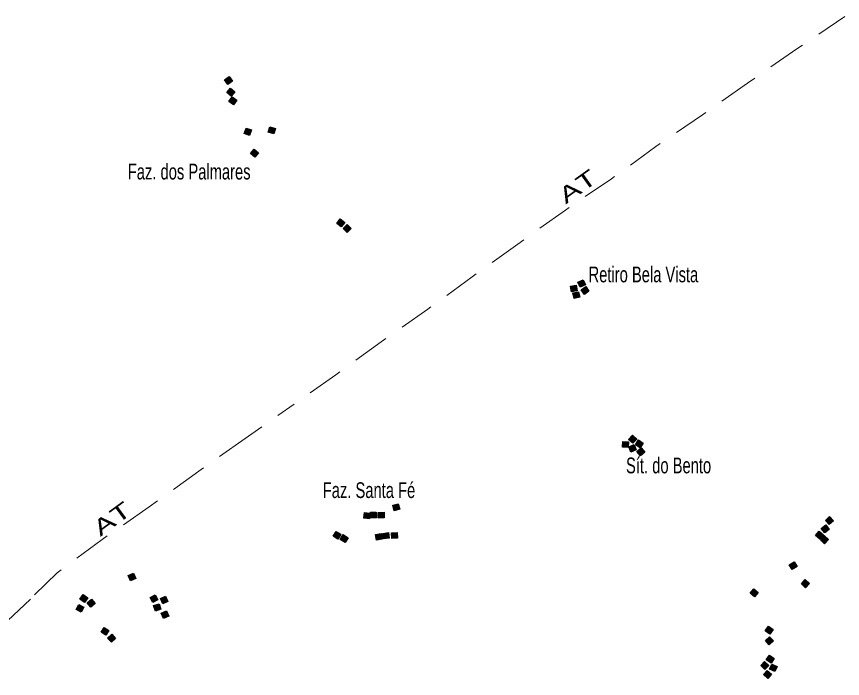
# Model space of a CAD drawing. Extents: x 679 to 705, y 7427.4 to 7455.4.
# Drawn here: x 683.784 to 687.983, y 7433.767 to 7437.132 of the extents above; entities that cross this region are included whole.
import ezdxf
from ezdxf.enums import TextEntityAlignment as Align

# ---------------------------------------------------------------- set-up
doc = ezdxf.new("R2010")
doc.units = 0
doc.header["$LTSCALE"] = 0.032
doc.linetypes.add('DOT_DASHED', pattern=[7.7, 5, -1.2, 0.3, -1.2])
doc.layers.add('2', color=7, linetype='Continuous', lineweight=25)
doc.layers.add('56', color=7, linetype='DOT_DASHED', lineweight=13)
doc.layers.add('61', color=7, linetype='Continuous')

msp = doc.modelspace()

# ---------------------------------------------------------------- hatches: boundary and pattern name
at = {"layer": '2'}
for points in [[(684.8648, 7436.8274), (684.8813, 7436.8036), (684.8575, 7436.787), (684.8409, 7436.8109)], [(684.871, 7436.7685), (684.8931, 7436.7497), (684.8743, 7436.7276), (684.8522, 7436.7465)], [(684.8804, 7436.7233), (684.9042, 7436.7066), (684.8876, 7436.6829), (684.8638, 7436.6995)], [(684.9779, 7436.5554), (684.9682, 7436.528), (684.9409, 7436.5377), (684.9505, 7436.5651)], [(685.0997, 7436.5632), (685.0913, 7436.5354), (685.0635, 7436.5439), (685.072, 7436.5716)], [(685.0135, 7436.4391), (684.9949, 7436.4169), (684.9727, 7436.4355), (684.9913, 7436.4577)], [(685.4299, 7436.1031), (685.4528, 7436.0852), (685.4349, 7436.0624), (685.4121, 7436.0803)], [(685.4441, 7436.0544), (685.4649, 7436.0746), (685.4851, 7436.0539), (685.4644, 7436.0336)], [(686.6642, 7435.7943), (686.6763, 7435.7679), (686.6499, 7435.7559), (686.6378, 7435.7822)], [(686.6296, 7435.7665), (686.6339, 7435.7378), (686.6053, 7435.7335), (686.601, 7435.7622)], [(686.6775, 7435.76), (686.6943, 7435.7364), (686.6707, 7435.7196), (686.6539, 7435.7432)], [(686.6412, 7435.7334), (686.6474, 7435.7051), (686.6191, 7435.6989), (686.6129, 7435.7272)], [(686.9152, 7435.0038), (686.9369, 7434.9846), (686.9177, 7434.9628), (686.896, 7434.982)], [(686.896, 7434.9707), (686.894, 7434.9418), (686.865, 7434.9438), (686.867, 7434.9727)], [(686.9243, 7434.9559), (686.9347, 7434.9288), (686.9076, 7434.9184), (686.8972, 7434.9455)], [(686.9467, 7434.9796), (686.9705, 7434.963), (686.954, 7434.9392), (686.9301, 7434.9558)], [(686.9602, 7434.9405), (686.9789, 7434.9184), (686.9567, 7434.8997), (686.938, 7434.9218)], [(685.7245, 7434.6554), (685.7321, 7434.6274), (685.7041, 7434.6198), (685.6965, 7434.6478)], [(685.581, 7434.6073), (685.5781, 7434.5785), (685.5492, 7434.5814), (685.5521, 7434.6102)], [(685.613, 7434.6134), (685.6138, 7434.5844), (685.5849, 7434.5835), (685.584, 7434.6125)], [(685.6521, 7434.6122), (685.6534, 7434.5832), (685.6245, 7434.5819), (685.6231, 7434.6108)], [(687.9178, 7434.5903), (687.9371, 7434.5688), (687.9156, 7434.5494), (687.8962, 7434.5709)], [(687.8981, 7434.548), (687.9158, 7434.5251), (687.8929, 7434.5074), (687.8752, 7434.5303)], [(685.4082, 7434.5152), (685.4329, 7434.5001), (685.4178, 7434.4753), (685.3931, 7434.4905)], [(685.4449, 7434.4984), (685.4695, 7434.483), (685.4541, 7434.4584), (685.4295, 7434.4738)], [(685.6381, 7434.5036), (685.642, 7434.4749), (685.6133, 7434.471), (685.6094, 7434.4997)], [(685.6744, 7434.5094), (685.6787, 7434.4807), (685.65, 7434.4764), (685.6458, 7434.5051)], [(685.7197, 7434.5094), (685.7207, 7434.4804), (685.6917, 7434.4794), (685.6907, 7434.5084)], [(687.8646, 7434.5157), (687.8867, 7434.4969), (687.8678, 7434.4749), (687.8458, 7434.4937)], [(687.8906, 7434.4933), (687.912, 7434.4737), (687.8924, 7434.4523), (687.871, 7434.4719)], [(687.7371, 7434.3607), (687.7524, 7434.3361), (687.7277, 7434.3208), (687.7124, 7434.3454)], [(684.3777, 7434.3025), (684.39, 7434.2762), (684.3638, 7434.2639), (684.3515, 7434.2902)], [(687.7933, 7434.2697), (687.815, 7434.2505), (687.7958, 7434.2288), (687.7741, 7434.248)], [(684.1218, 7434.1935), (684.1456, 7434.177), (684.1291, 7434.1531), (684.1053, 7434.1697)], [(684.4879, 7434.1932), (684.5021, 7434.1679), (684.4768, 7434.1537), (684.4626, 7434.179)], [(684.5415, 7434.1857), (684.5535, 7434.1593), (684.5271, 7434.1473), (684.5151, 7434.1737)], [(687.5333, 7434.2233), (687.5551, 7434.2041), (687.5359, 7434.1824), (687.5141, 7434.2016)], [(684.0997, 7434.1436), (684.1254, 7434.1304), (684.1122, 7434.1046), (684.0864, 7434.1179)], [(684.1649, 7434.1699), (684.1835, 7434.1476), (684.1612, 7434.1291), (684.1426, 7434.1513)], [(684.5081, 7434.147), (684.5175, 7434.1196), (684.4901, 7434.1102), (684.4806, 7434.1376)], [(684.5462, 7434.111), (684.5575, 7434.0843), (684.5308, 7434.073), (684.5195, 7434.0997)], [(684.229, 7434.0271), (684.2536, 7434.0117), (684.2382, 7433.9871), (684.2136, 7434.0025)], [(687.6075, 7434.0331), (687.6307, 7434.0156), (687.6133, 7433.9924), (687.5901, 7434.0099)], [(684.268, 7433.9925), (684.2875, 7433.9711), (684.2661, 7433.9515), (684.2465, 7433.973)], [(687.6129, 7433.9798), (687.6321, 7433.9581), (687.6103, 7433.9389), (687.5911, 7433.9607)], [(687.5875, 7433.8533), (687.6083, 7433.8331), (687.5881, 7433.8123), (687.5673, 7433.8326)], [(687.6123, 7433.8853), (687.6362, 7433.8689), (687.6199, 7433.845), (687.5959, 7433.8613)], [(687.6009, 7433.8083), (687.6224, 7433.7888), (687.6029, 7433.7673), (687.5814, 7433.7868)], [(687.6245, 7433.8407), (687.6509, 7433.8288), (687.639, 7433.8024), (687.6126, 7433.8143)]]:
    msp.add_hatch(color=256, dxfattribs=at).paths.add_polyline_path(points)

# ---------------------------------------------------------------- linework, layer by layer
for points in [[(684.8648, 7436.8274), (684.8813, 7436.8036), (684.8575, 7436.787), (684.8409, 7436.8109)], [(684.871, 7436.7685), (684.8931, 7436.7497), (684.8743, 7436.7276), (684.8522, 7436.7465)], [(684.8804, 7436.7233), (684.9042, 7436.7066), (684.8876, 7436.6829), (684.8638, 7436.6995)], [(684.9779, 7436.5554), (684.9682, 7436.528), (684.9409, 7436.5377), (684.9505, 7436.5651)], [(685.0997, 7436.5632), (685.0913, 7436.5354), (685.0635, 7436.5439), (685.072, 7436.5716)], [(685.0135, 7436.4391), (684.9949, 7436.4169), (684.9727, 7436.4355), (684.9913, 7436.4577)], [(685.4299, 7436.1031), (685.4528, 7436.0852), (685.4349, 7436.0624), (685.4121, 7436.0803)], [(685.4441, 7436.0544), (685.4649, 7436.0746), (685.4851, 7436.0539), (685.4644, 7436.0336)], [(686.6642, 7435.7943), (686.6763, 7435.7679), (686.6499, 7435.7559), (686.6378, 7435.7822)], [(686.6296, 7435.7665), (686.6339, 7435.7378), (686.6053, 7435.7335), (686.601, 7435.7622)], [(686.6775, 7435.76), (686.6943, 7435.7364), (686.6707, 7435.7196), (686.6539, 7435.7432)], [(686.6412, 7435.7334), (686.6474, 7435.7051), (686.6191, 7435.6989), (686.6129, 7435.7272)], [(686.9152, 7435.0038), (686.9369, 7434.9846), (686.9177, 7434.9628), (686.896, 7434.982)], [(686.896, 7434.9707), (686.894, 7434.9418), (686.865, 7434.9438), (686.867, 7434.9727)], [(686.9243, 7434.9559), (686.9347, 7434.9288), (686.9076, 7434.9184), (686.8972, 7434.9455)], [(686.9467, 7434.9796), (686.9705, 7434.963), (686.954, 7434.9392), (686.9301, 7434.9558)], [(686.9602, 7434.9405), (686.9789, 7434.9184), (686.9567, 7434.8997), (686.938, 7434.9218)], [(685.7245, 7434.6554), (685.7321, 7434.6274), (685.7041, 7434.6198), (685.6965, 7434.6478)], [(685.581, 7434.6073), (685.5781, 7434.5785), (685.5492, 7434.5814), (685.5521, 7434.6102)], [(685.613, 7434.6134), (685.6138, 7434.5844), (685.5849, 7434.5835), (685.584, 7434.6125)], [(685.6521, 7434.6122), (685.6534, 7434.5832), (685.6245, 7434.5819), (685.6231, 7434.6108)], [(687.9178, 7434.5903), (687.9371, 7434.5688), (687.9156, 7434.5494), (687.8962, 7434.5709)], [(687.8981, 7434.548), (687.9158, 7434.5251), (687.8929, 7434.5074), (687.8752, 7434.5303)], [(685.4082, 7434.5152), (685.4329, 7434.5001), (685.4178, 7434.4753), (685.3931, 7434.4905)], [(685.4449, 7434.4984), (685.4695, 7434.483), (685.4541, 7434.4584), (685.4295, 7434.4738)], [(685.6381, 7434.5036), (685.642, 7434.4749), (685.6133, 7434.471), (685.6094, 7434.4997)], [(685.6744, 7434.5094), (685.6787, 7434.4807), (685.65, 7434.4764), (685.6458, 7434.5051)], [(685.7197, 7434.5094), (685.7207, 7434.4804), (685.6917, 7434.4794), (685.6907, 7434.5084)], [(687.8646, 7434.5157), (687.8867, 7434.4969), (687.8678, 7434.4749), (687.8458, 7434.4937)], [(687.8906, 7434.4933), (687.912, 7434.4737), (687.8924, 7434.4523), (687.871, 7434.4719)], [(687.7371, 7434.3607), (687.7524, 7434.3361), (687.7277, 7434.3208), (687.7124, 7434.3454)], [(684.3777, 7434.3025), (684.39, 7434.2762), (684.3638, 7434.2639), (684.3515, 7434.2902)], [(687.7933, 7434.2697), (687.815, 7434.2505), (687.7958, 7434.2288), (687.7741, 7434.248)], [(684.1218, 7434.1935), (684.1456, 7434.177), (684.1291, 7434.1531), (684.1053, 7434.1697)], [(684.4879, 7434.1932), (684.5021, 7434.1679), (684.4768, 7434.1537), (684.4626, 7434.179)], [(684.5415, 7434.1857), (684.5535, 7434.1593), (684.5271, 7434.1473), (684.5151, 7434.1737)], [(687.5333, 7434.2233), (687.5551, 7434.2041), (687.5359, 7434.1824), (687.5141, 7434.2016)], [(684.0997, 7434.1436), (684.1254, 7434.1304), (684.1122, 7434.1046), (684.0864, 7434.1179)], [(684.1649, 7434.1699), (684.1835, 7434.1476), (684.1612, 7434.1291), (684.1426, 7434.1513)], [(684.5081, 7434.147), (684.5175, 7434.1196), (684.4901, 7434.1102), (684.4806, 7434.1376)], [(684.5462, 7434.111), (684.5575, 7434.0843), (684.5308, 7434.073), (684.5195, 7434.0997)], [(684.229, 7434.0271), (684.2536, 7434.0117), (684.2382, 7433.9871), (684.2136, 7434.0025)], [(687.6075, 7434.0331), (687.6307, 7434.0156), (687.6133, 7433.9924), (687.5901, 7434.0099)], [(684.268, 7433.9925), (684.2875, 7433.9711), (684.2661, 7433.9515), (684.2465, 7433.973)], [(687.6129, 7433.9798), (687.6321, 7433.9581), (687.6103, 7433.9389), (687.5911, 7433.9607)], [(687.5875, 7433.8533), (687.6083, 7433.8331), (687.5881, 7433.8123), (687.5673, 7433.8326)], [(687.6123, 7433.8853), (687.6362, 7433.8689), (687.6199, 7433.845), (687.5959, 7433.8613)], [(687.6009, 7433.8083), (687.6224, 7433.7888), (687.6029, 7433.7673), (687.5814, 7433.7868)], [(687.6245, 7433.8407), (687.6509, 7433.8288), (687.639, 7433.8024), (687.6126, 7433.8143)]]:
    msp.add_lwpolyline(points, close=True, dxfattribs=at)
at = {"layer": '56'}
msp.add_lwpolyline([(687.995, 7437.1322), (687.7505, 7436.9673), (687.501, 7436.7939), (687.2714, 7436.6328), (687.0347, 7436.4715), (686.808, 7436.3066), (686.5748, 7436.1484), (686.3318, 7435.9753), (686.1005, 7435.8088), (685.8753, 7435.6447), (685.638, 7435.4789), (685.4079, 7435.311), (684.947, 7434.9879), (684.7113, 7434.8215), (684.4585, 7434.6402), (684.2196, 7434.4743), (683.99, 7434.3042), (683.8542, 7434.1713), (683.6453, 7433.9724)], dxfattribs=at)

# ---------------------------------------------------------------- texts
at = {"layer": '61', "width": 0.7}
for s, p in [('Faz. dos Palmares', (684.3494, 7436.3038)), ('Retiro Bela Vista', (686.6921, 7435.7811)), ('Sít. do Bento', (686.8826, 7434.8102)), ('Faz. Santa Fé', (685.3407, 7434.6846))]:
    msp.add_text(s, height=0.08, dxfattribs=at).set_placement(p)
at = {"layer": '61', "width": 1.5}
for rotation, p in [(35.472, (686.6599, 7436.2361)), (36.165, (684.2926, 7434.5469))]:
    msp.add_text('AT', height=0.08, rotation=rotation, dxfattribs=at).set_placement(p, align=Align.CENTER)

doc.saveas('drawing.dxf')
